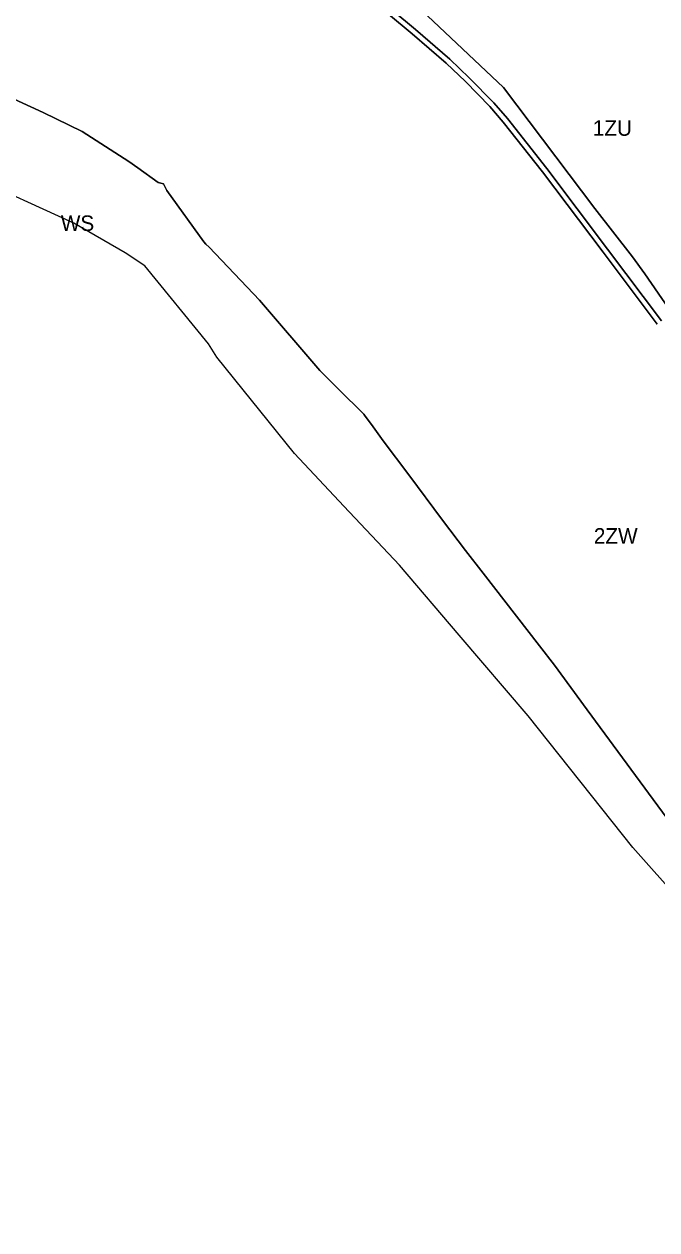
# Model space of a CAD drawing. Extents: x -300162 to -296646, y 29434 to 30761.
# Drawn here: x -298414 to -298006, y 29437 to 30215 of the extents above; entities that cross this region are included whole.
import ezdxf

# ---------------------------------------------------------------- set-up
doc = ezdxf.new("R2010")
doc.units = 0
doc.layers.add('linie_rozgraniczajace', color=7, linetype='Continuous')
doc.layers.add('oznaczenia_przeznaczen', color=7, linetype='Continuous')

msp = doc.modelspace()

# ---------------------------------------------------------------- linework, layer by layer
at = {"layer": 'linie_rozgraniczajace'}
for points in [[(-298003.332, 30023.503), (-298038.093, 30069.754), (-298077.145, 30121.715), (-298102.668, 30153.889), (-298111.404, 30164.079), (-298127.284, 30180.219), (-298139.72, 30192.22), (-298161.824, 30211.345), (-298177.067, 30224.095)], [(-298177.067, 30224.095), (-298161.824, 30211.345), (-298139.72, 30192.22), (-298127.284, 30180.219), (-298111.404, 30164.079), (-298102.668, 30153.889), (-298077.145, 30121.715), (-298038.093, 30069.754), (-298003.332, 30023.503)], [(-298179.222, 30221.335), (-298164.092, 30208.679), (-298142.082, 30189.636), (-298129.747, 30177.732), (-298113.983, 30161.71), (-298105.368, 30151.661), (-298079.915, 30119.576), (-298040.891, 30067.651), (-298006.13, 30021.4)], [(-298006.13, 30021.4), (-298040.891, 30067.651), (-298079.915, 30119.576), (-298105.368, 30151.661), (-298113.983, 30161.71), (-298129.747, 30177.732), (-298142.082, 30189.636), (-298164.092, 30208.679), (-298179.222, 30221.335)], [(-297987.76, 30015.69), (-298013.94, 30053.73), (-298021.89, 30064.83), (-298046.34, 30095.85), (-298105.21, 30173.96), (-298154.08, 30220.18)], [(-298154.08, 30220.18), (-298105.21, 30173.96), (-298046.34, 30095.85), (-298021.89, 30064.83), (-298013.94, 30053.73), (-297987.76, 30015.69)], [(-298428.699, 30170.119), (-298402.082, 30157.771), (-298376.996, 30145.596), (-298346.829, 30126.156), (-298341.098, 30122.052), (-298327.969, 30112.65), (-298324.48, 30111.894), (-298322.328, 30107.59), (-298298.503, 30074.421), (-298297.194, 30072.899)], [(-297951.586, 29637.393), (-298051.094, 29772.591), (-298072.295, 29801.395), (-298081.879, 29813.931), (-298096.825, 29833.046), (-298118.286, 29860.739), (-298129.572, 29875.303), (-298144.462, 29894.989), (-298166.251, 29924.087), (-298182.66, 29945.999), (-298189.301, 29955.095), (-298194.821, 29962.655), (-298195.202, 29963.177), (-298196.183, 29964.11), (-298201.098, 29968.975), (-298205.834, 29973.665), (-298207.887, 29975.698), (-298216.184, 29983.913), (-298223.527, 29991.371), (-298262.464, 30036.88), (-298294.955, 30070.912), (-298297.194, 30072.899), (-298298.503, 30074.421), (-298322.328, 30107.59), (-298324.48, 30111.894), (-298327.969, 30112.65), (-298341.098, 30122.052), (-298346.829, 30126.156), (-298376.996, 30145.596), (-298402.082, 30157.771), (-298428.699, 30170.119)], [(-297343.9, 29437.13), (-297510, 29447.37), (-297600.03, 29466.88), (-297623.03, 29471.65), (-297685.72, 29479.9), (-297751.84, 29500), (-297788.27, 29510.52), (-297861.05, 29532.95), (-297915.32, 29578.84), (-297959.37, 29613.67), (-298021.78, 29683.83), (-298089.26, 29768.65), (-298133.84, 29820.72), (-298172.27, 29865.83), (-298208.12, 29903.83), (-298240, 29938), (-298289.95, 30000), (-298295.47, 30008.63), (-298336.46, 30059.03), (-298349.16, 30067.38), (-298382.23, 30086.44), (-298449.27, 30117)], [(-298297.194, 30072.899), (-298294.955, 30070.912), (-298262.464, 30036.88), (-298223.527, 29991.371), (-298216.184, 29983.913), (-298207.887, 29975.698), (-298205.834, 29973.665), (-298201.098, 29968.975), (-298196.183, 29964.11), (-298195.202, 29963.177), (-298194.821, 29962.655), (-298189.301, 29955.095), (-298182.66, 29945.999), (-298166.251, 29924.087), (-298144.462, 29894.989), (-298129.572, 29875.303), (-298118.286, 29860.739), (-298096.825, 29833.046), (-298081.879, 29813.931), (-298072.295, 29801.395), (-298051.094, 29772.591), (-297951.586, 29637.393)]]:
    msp.add_lwpolyline(points, dxfattribs=at)

# ---------------------------------------------------------------- texts
at = {"layer": 'oznaczenia_przeznaczen'}
for s, p in [('1ZU', (-298047.541434, 30142.830001)), ('WS', (-298390.690213, 30081.440001)), ('2ZW', (-298046.866492, 29879.770001))]:
    msp.add_text(s, height=10, dxfattribs=at).set_placement(p)

doc.saveas('drawing.dxf')
